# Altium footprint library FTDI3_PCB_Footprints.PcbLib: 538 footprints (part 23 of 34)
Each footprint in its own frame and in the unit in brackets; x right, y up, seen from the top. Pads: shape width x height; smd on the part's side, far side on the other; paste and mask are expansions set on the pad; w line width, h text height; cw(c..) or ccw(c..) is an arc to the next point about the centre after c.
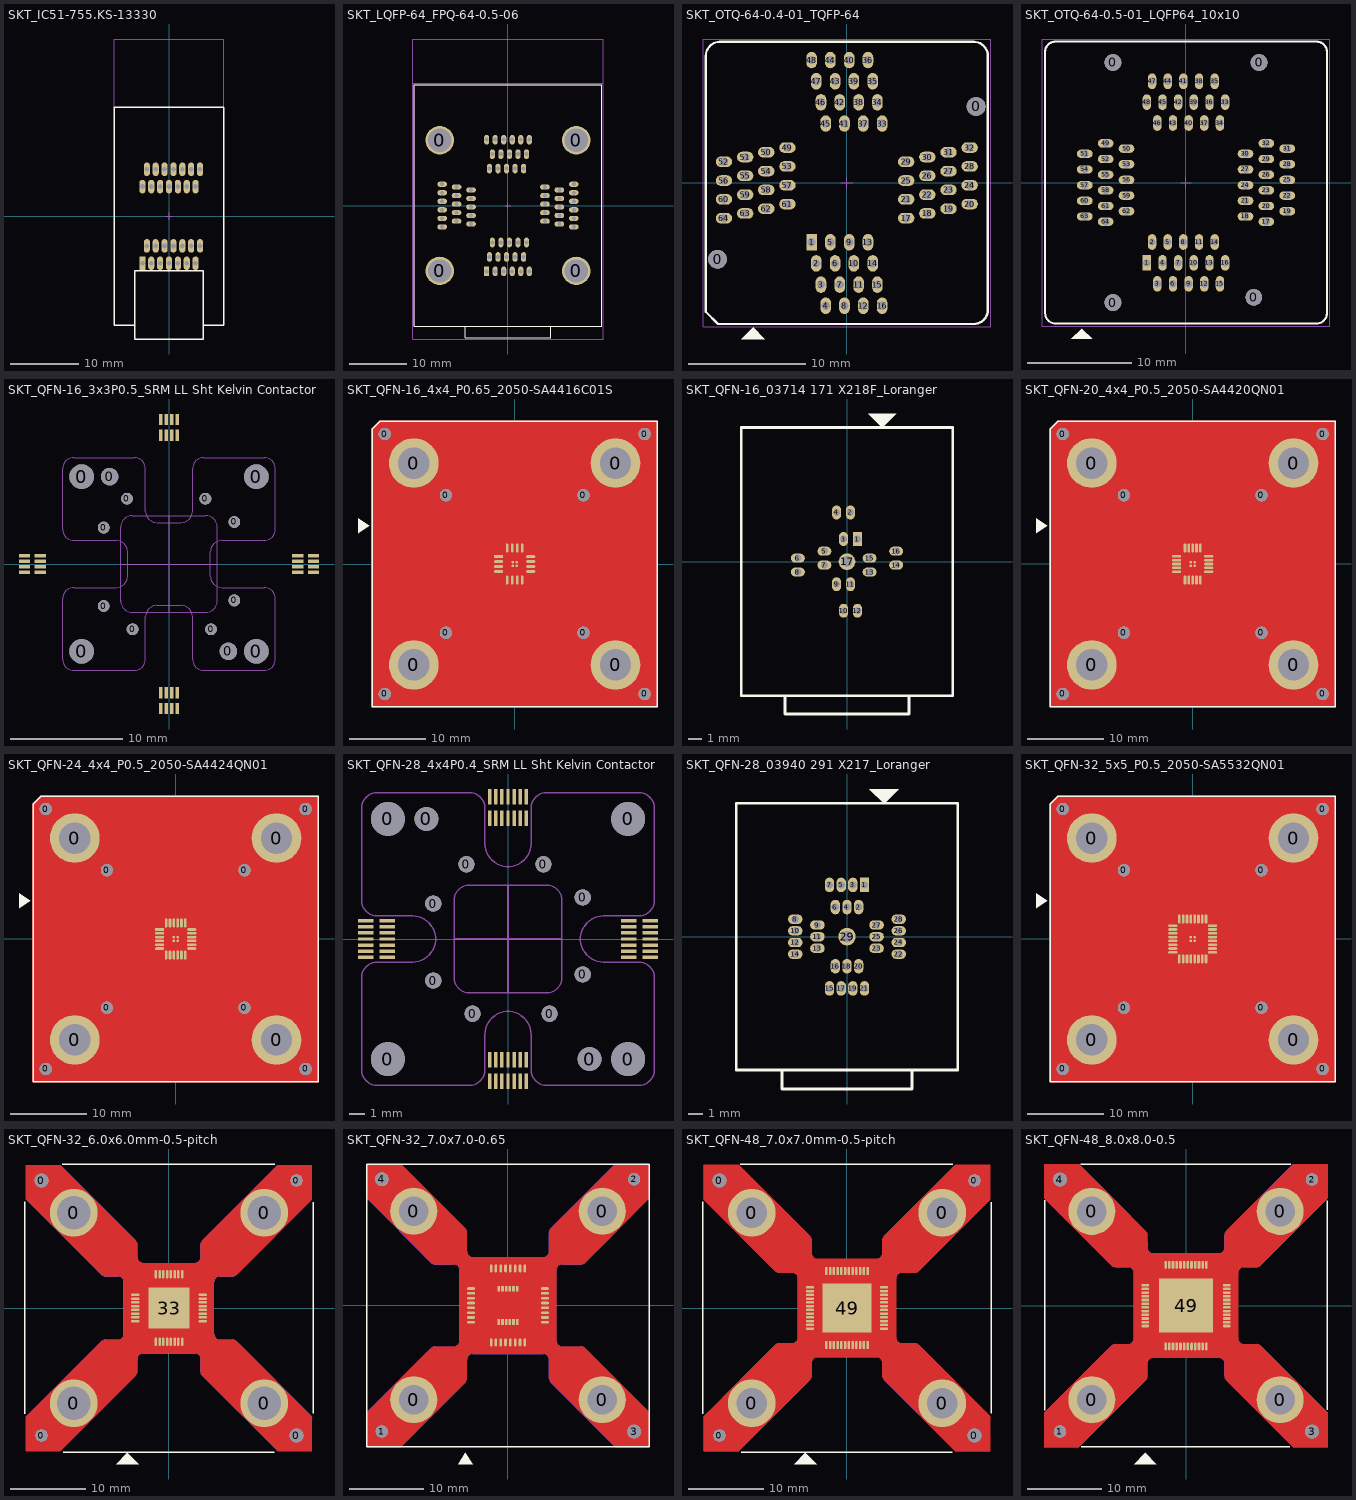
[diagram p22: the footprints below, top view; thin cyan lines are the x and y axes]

## SKT_IC51-755.KS-13330 [mm] "CLAMSHELL SOCKET 28PIN SSOP; Yamaichi - IC51-755.KS-13330"
height 20
pads (28):
  rect 0.9x2 hole 0.7: 1(-3.9,-6.89)
  oval 0.9x2 hole 0.7: 2(-3.25,-4.35) 3(-2.6,-6.89) 4(-1.95,-4.35) 5(-1.3,-6.89) 6(-0.65,-4.35) 7(0,-6.89) 8(0.65,-4.35) 9(1.3,-6.89) 10(1.95,-4.35) 11(2.6,-6.89) 12(3.25,-4.35) 13(3.9,-6.89) 14(4.55,-4.35) 15(4.55,6.89) 16(3.9,4.35) 17(3.25,6.89) 18(2.6,4.35) 19(1.95,6.89) 20(1.3,4.35) 21(0.65,6.89) 22(0,4.35) 23(-0.65,6.89) 24(-1.3,4.35) 25(-1.95,6.89) 26(-2.6,4.35) 27(-3.25,6.89) 28(-3.9,4.35)
Top Overlay:
  lines w0.2: -5,-16 -8,-16 -8,16 8,16 8,-16 5,-16 ; -5,-18 5,-18 5,-8 -5,-8 -5,-18
M15_Country_Yard:
  lines w0.1: -8,16 -8,26 8,26 8,16 ; -0.5,0 0.5,0 ; 0,-0.5 0,0.5

## SKT_LQFP-64_FPQ-64-0.5-06 [mm] "Test & Burn socket for LQFP-64, 0.5mm pitch, 10x10mm body. Enplas FPQ-64-0.5-06"
height 16
pads (68):
  round 5 hole 4.1: 0(-12,-11.5) 0(-12,11.5) 0(12,-11.5) 0(12,11.5)
  rect 0.9x1.7 hole 0.7: 1(-3.751,-11.582)
  oval 0.9x1.7 hole 0.7: 2(-3.251,-9.042) 3(-2.751,-6.502) 4(-2.251,-11.582) 5(-1.751,-9.042) 6(-1.251,-6.502) 7(-0.751,-11.582) 8(-0.251,-9.042) 9(0.249,-6.502) 10(0.749,-11.582) 11(1.249,-9.042) 12(1.749,-6.502) 13(2.249,-11.582) 14(2.749,-9.042) 15(3.249,-6.502) 16(3.749,-11.582) 33(3.749,11.582) 34(3.249,9.042) 35(2.749,6.502) 36(2.249,11.582) 37(1.749,9.042) 38(1.249,6.502) 39(0.749,11.582) 40(0.249,9.042) 41(-0.251,6.502) 42(-0.751,11.582) 43(-1.251,9.042) 44(-1.751,6.502) 45(-2.251,11.582) 46(-2.751,9.042) 47(-3.251,6.502) 48(-3.751,11.582)
  oval 1.7x0.9 hole 0.7: 17(11.582,-3.751) 18(9.042,-3.251) 19(6.502,-2.751) 20(11.582,-2.251) 21(9.042,-1.751) 22(6.502,-1.251) 23(11.582,-0.751) 24(9.042,-0.251) 25(6.502,0.249) 26(11.582,0.749) 27(9.042,1.249) 28(6.502,1.749) 29(11.582,2.249) 30(9.042,2.749) 31(6.502,3.249) 32(11.582,3.749) 49(-11.583,3.749) 50(-9.043,3.249) 51(-6.503,2.749) 52(-11.583,2.249) 53(-9.043,1.749) 54(-6.503,1.249) 55(-11.583,0.749) 56(-9.043,0.249) 57(-6.503,-0.251) 58(-11.583,-0.751) 59(-9.043,-1.251) 60(-6.503,-1.751) 61(-11.583,-2.251) 62(-9.043,-2.751) 63(-6.503,-3.251) 64(-11.583,-3.751)
Top Overlay:
  lines w0.2: -7.501,-21.25 -7.501,-23.24 7.499,-23.24 7.499,-21.25 ; -16.5,-21.25 -16.5,21.25 16.5,21.25 16.5,-21.25 -16.5,-21.25
M13_Assembly_Info:
  lines w0.1: -16.5,-21.25 -16.5,21.25 16.5,21.25 16.5,-21.25 -16.5,-21.25
M15_Country_Yard:
  lines w0.1: -16.74,21.51 16.75,21.51 ; -0.5,0 0.5,0 ; 0,-0.5 0,0.5 ; -16.74,-23.48 -16.74,-21.01 -16.74,21.25 -16.74,29.3 16.75,29.3 16.75,21.25 16.75,-21 16.75,-23.48 -16.74,-23.48

## SKT_OTQ-64-0.4-01_TQFP-64 [mm] "Test & Burn socket for TQFP-64 package"
height 19
pads (66):
  round 1.6 hole 1.6 unplated: 0(-11,-6.5) 0(11,6.5)
  rect 0.9x1.4 hole 0.7: 1(-3,-5.05)
  oval 0.9x1.4 hole 0.7: 2(-2.6,-6.85) 3(-2.2,-8.65) 4(-1.8,-10.45) 5(-1.4,-5.05) 6(-1,-6.85) 7(-0.6,-8.65) 8(-0.2,-10.45) 9(0.2,-5.05) 10(0.6,-6.85) 11(1,-8.65) 12(1.4,-10.45) 13(1.8,-5.05) 14(2.2,-6.85) 15(2.6,-8.65) 16(3,-10.45) 33(3,5.05) 34(2.6,6.85) 35(2.2,8.65) 36(1.8,10.45) 37(1.4,5.05) 38(1,6.85) 39(0.6,8.65) 40(0.2,10.45) 41(-0.2,5.05) 42(-0.6,6.85) 43(-1,8.65) 44(-1.4,10.45) 45(-1.8,5.05) 46(-2.2,6.85) 47(-2.6,8.65) 48(-3,10.45)
  oval 1.4x0.9 hole 0.7: 17(5.05,-3) 18(6.85,-2.6) 19(8.65,-2.2) 20(10.45,-1.8) 21(5.05,-1.4) 22(6.85,-1) 23(8.65,-0.6) 24(10.45,-0.2) 25(5.05,0.2) 26(6.85,0.6) 27(8.65,1) 28(10.45,1.4) 29(5.05,1.8) 30(6.85,2.2) 31(8.65,2.6) 32(10.45,3) 49(-5.05,3) 50(-6.85,2.6) 51(-8.65,2.2) 52(-10.45,1.8) 53(-5.05,1.4) 54(-6.85,1) 55(-8.65,0.6) 56(-10.45,0.2) 57(-5.05,-0.2) 58(-6.85,-0.6) 59(-8.65,-1) 60(-10.45,-1.4) 61(-5.05,-1.8) 62(-6.85,-2.2) 63(-8.65,-2.6) 64(-10.45,-3)
Top Overlay:
  region: -7.98,-12.28 -8.98,-13.28 -6.98,-13.28
  lines w0.2: -12,-10.96 -12,10.8 cw(c-10.8,10.8) -10.8,12 10.8,12 cw(c10.8,10.8) 12,10.8 12,-10.8 cw(c10.8,-10.8) 10.8,-12 -10.96,-12 -12,-10.96
M15_Country_Yard:
  lines w0.1: -0.5,0 0.5,0 ; 0,-0.5 0,0.5 ; -12.23,-12.25 -12.23,12.24 12.26,12.24 12.26,-12.25 -12.23,-12.25

## SKT_OTQ-64-0.5-01_LQFP64_10x10 [mm] "http://wvshare.com/product/OTQ-64-0.5-01.htm"
height 16
pads (68):
  round 1.6 hole 1.6 unplated: 0(-7,-11.5) 0(-7,11.5) 0(6.5,-11) 0(7,11.5)
  rect 0.8x1.5 hole 0.7: 1(-3.75,-7.7)
  oval 0.8x1.5 hole 0.7: 2(-3.25,-5.7) 3(-2.75,-9.7) 4(-2.25,-7.7) 5(-1.75,-5.7) 6(-1.25,-9.7) 7(-0.75,-7.7) 8(-0.25,-5.7) 9(0.25,-9.7) 10(0.75,-7.7) 11(1.25,-5.7) 12(1.75,-9.7) 13(2.25,-7.7) 14(2.75,-5.7) 15(3.25,-9.7) 16(3.75,-7.7) 33(3.75,7.7) 34(3.25,5.7) 35(2.75,9.7) 36(2.25,7.7) 37(1.75,5.7) 38(1.25,9.7) 39(0.75,7.7) 40(0.25,5.7) 41(-0.25,9.7) 42(-0.75,7.7) 43(-1.25,5.7) 44(-1.75,9.7) 45(-2.25,7.7) 46(-2.75,5.7) 47(-3.25,9.7) 48(-3.75,7.7)
  oval 1.5x0.8 hole 0.7: 17(7.7,-3.75) 18(5.7,-3.25) 19(9.7,-2.75) 20(7.7,-2.25) 21(5.7,-1.75) 22(9.7,-1.25) 23(7.7,-0.75) 24(5.7,-0.25) 25(9.7,0.25) 26(7.7,0.75) 27(5.7,1.25) 28(9.7,1.75) 29(7.7,2.25) 30(5.7,2.75) 31(9.7,3.25) 32(7.7,3.75) 49(-7.7,3.75) 50(-5.7,3.25) 51(-9.7,2.75) 52(-7.7,2.25) 53(-5.7,1.75) 54(-9.7,1.25) 55(-7.7,0.75) 56(-5.7,0.25) 57(-9.7,-0.25) 58(-7.7,-0.75) 59(-5.7,-1.25) 60(-9.7,-1.75) 61(-7.7,-2.25) 62(-5.7,-2.75) 63(-9.7,-3.25) 64(-7.7,-3.75)
Top Overlay:
  region: -10,-13.99 -11,-14.99 -9,-14.99
  lines w0.2: -13.5,-12.5 -13.5,12.51 cw(c-12.51,12.51) -12.51,13.5 12.51,13.5 cw(c12.51,12.51) 13.5,12.51 13.5,-12.51 cw(c12.51,-12.51) 12.51,-13.5 -12.5,-13.5 cw(c-12.5,-12.51) -13.49,-12.51
M15_Country_Yard:
  lines w0.1: -0.5,0 0.5,0 ; 0,-0.5 0,0.5 ; -13.75,-13.75 13.75,-13.75 13.75,13.35 13.75,13.75 -13.75,13.75 -13.75,-13.75
3D body: height 16, standoff 0, extent -13.5,-13.5 13.5,13.5
3D body: height 16, standoff 0, extent -5,-5 5,5

## SKT_QFN-16_3x3P0.5_SRM LL Sht Kelvin Contactor [mm] "Test Socket for QFN-16; 3x3mm package; 0.5mm pitch; SRM LL Sht Kelvin Contactor"
height 18
pads (46):
  round 2.2 hole 2.2 unplated: 0(-7.8,-7.8) 0(-7.8,7.8) 0(7.8,-7.8) 0(7.8,7.8)
  round 1.05 hole 1.05 unplated: 0(-5.83,-3.75) 0(-5.83,3.25) 0(-3.75,5.83) 0(-3.25,-5.83) 0(3.25,5.83) 0(3.75,-5.83) 0(5.83,-3.25) 0(5.83,3.75)
  round 1.55 hole 1.55 unplated: 0(-5.3,7.8) 0(5.3,-7.8)
  rect 1x0.3 smd: 1(11.49,-0.75) 1(12.89,-0.75) 2(11.49,-0.25) 2(12.89,-0.25) 3(11.49,0.25) 3(12.89,0.25) 4(11.49,0.75) 4(12.89,0.75) 9(-12.89,0.75) 9(-11.49,0.75) 10(-12.89,0.25) 10(-11.49,0.25) 11(-12.89,-0.25) 11(-11.49,-0.25) 12(-12.89,-0.75) 12(-11.49,-0.75)
  rect 0.3x1 smd: 5(0.75,11.49) 5(0.75,12.89) 6(0.25,11.49) 6(0.25,12.89) 7(-0.25,11.49) 7(-0.25,12.89) 8(-0.75,11.49) 8(-0.75,12.89) 13(-0.75,-12.89) 13(-0.75,-11.49) 14(-0.25,-12.89) 14(-0.25,-11.49) 15(0.25,-12.89) 15(0.25,-11.49) 16(0.75,-12.89) 16(0.75,-11.49)
Mechanical 1:
  lines w0.1: -4.3,-3.36 -4.3,3.3 cw(c-3.3,3.3) -3.3,4.3 3.3,4.3 cw(c3.3,3.3) 4.3,3.3 4.3,-3.3 cw(c3.3,-3.3) 3.3,-4.3 -3.3,-4.3 cw(c-3.3,-3.3) -4.3,-3.3
  text "area" at -3.19,-0.85 h0.8
  text "PCB Cutout" at -3.19,0.2 h0.8
M15_Country_Yard:
  lines w0.1: -4.3,0 4.3,0 ; -3.75,0 0,0 ; 0,-4.3 0,4.3 ; 0,-3.75 0,0 ; 0,3.75 0,0 ; 3.75,0 0,0 ; 0,0 0,-3.7 0,3.7 0,0 ; 0,0 -3.7,0 3.7,0 0,0 ; -9.5,-8.5 ccw(c-8.5,-8.5) -8.5,-9.5 -3.1,-9.5 ccw(c-3.1,-8.5) -2.1,-8.5 -2.1,-4.7 cw(c-1.1,-4.7) -1.1,-3.7 1.1,-3.7 cw(c1.1,-4.7) 2.1,-4.7 2.1,-8.5 ccw(c3.1,-8.5) 3.1,-9.5 8.5,-9.5 ccw(c8.5,-8.5) 9.5,-8.5 9.5,-3.1 ccw(c8.5,-3.1) 8.5,-2.1 4.7,-2.1 cw(c4.7,-1.1) 3.7,-1.1 3.7,1.1 cw(c4.7,1.1) 4.7,2.1 8.5,2.1 ccw(c8.5,3.1) 9.5,3.1 9.5,8.5 ccw(c8.5,8.5) 8.5,9.5 3.1,9.5 ccw(c3.1,8.5) 2.1,8.5 2.1,4.7 cw(c1.1,4.7) 1.1,3.7 -1.1,3.7 cw(c-1.1,4.7) -2.1,4.7 -2.1,8.5 ccw(c-3.1,8.5) -3.1,9.5 -8.5,9.5 ccw(c-8.5,8.5) -9.5,8.5 -9.5,3.1 ccw(c-8.5,3.1) -8.5,2.1 -4.7,2.1 cw(c-4.7,1.1) -3.7,1.1 -3.7,-1.1 cw(c-4.7,-1.1) -4.7,-2.1 -8.5,-2.1 ccw(c-8.5,-3.1) -9.5,-3.1 -9.5,-8.5

## SKT_QFN-16_4x4_P0.65_2050-SA4416C01S [mm] "Tai-Chen Precision Inc. QFN-16 4x4mm body; 0.65mm pitch; Test Socket; 2050-SA4416C01S"
height 6.6
pads (32):
  round 1.6 hole 1.6 unplated: 0(-17,-17) 0(-17,17) 0(-9,-9) 0(-9,9) 0(9,-9) 0(9,9) 0(17,-17) 0(17,17)
  round 6.5 hole 4.1: 0(-13.2,-13.2) 0(-13.2,13.2) 0(13.2,-13.2) 0(13.2,13.2)
  rect 1.2x0.35 smd: 1(-2.1,0.97)
  oval 1.2x0.35 smd: 2(-2.1,0.32) 3(-2.1,-0.33) 4(-2.1,-0.98) 9(2.1,-0.98) 10(2.1,-0.33) 11(2.1,0.32) 12(2.1,0.97)
  oval 0.35x1.2 smd: 5(-0.98,-2.1) 6(-0.33,-2.1) 7(0.32,-2.1) 8(0.97,-2.1) 13(0.97,2.1) 14(0.32,2.1) 15(-0.33,2.1) 16(-0.98,2.1)
  round 0.35 smd: 17(-0.25,-0.25) 17(-0.25,0.25) 17(0.25,-0.25) 17(0.25,0.25)
Top Layer:
  pour cut-out: 18.75,18.75 18.75,-18.75 -18.75,-18.75 -18.75,17.69 -17.69,18.75
Top Overlay:
  region: -19,5 -20.5,4 -20.5,6
  lines w0.2: -18.65,-18.65 -18.65,17.65 -17.65,18.65 18.65,18.65 18.65,-18.65 -18.65,-18.65
Top Solder:
  region: -18.55,-18.55 -18.55,17.61 -17.61,18.55 18.55,18.55 18.55,-18.55
M15_Country_Yard:
  lines w0.1: -0.5,0 0.5,0 ; 0,-0.5 0,0.5

## SKT_QFN-16_03714 171 X218F_Loranger [mm] "Test&Burn In Socket for QFN-16; 3x3mm package; 0.5mm pitch; Loranger part No. 03714 171 X218F"
height 18
pads (17):
  rect 0.65x1 hole 0.5: 1(0.75,1.625)
  oval 0.65x1 hole 0.5: 2(0.25,3.535) 3(-0.25,1.625) 4(-0.75,3.535) 9(-0.75,-1.625) 10(-0.25,-3.535) 11(0.25,-1.625) 12(0.75,-3.535)
  oval 1x0.65 hole 0.5: 5(-1.625,0.75) 6(-3.535,0.25) 7(-1.625,-0.25) 8(-3.535,-0.75) 13(1.625,-0.75) 14(3.535,-0.25) 15(1.625,0.25) 16(3.535,0.75)
  round 1.2 hole 0.8: 17(0,0)
Top Overlay:
  region: 2.54,9.615 1.54,10.615 3.54,10.615
  lines w0.2: -4.45,-9.66 -4.45,-10.96 4.45,-10.96 4.45,-9.66 ; -7.6,-9.65 7.6,-9.65 7.6,9.65 -7.6,9.65 -7.6,-9.65
M15_Country_Yard:
  lines w0.1: -0.5,0 0.5,0 ; 0,-0.5 0,0.5

## SKT_QFN-20_4x4_P0.5_2050-SA4420QN01 [mm] "Tai-Chen Precision Inc. QFN-20 4x4mm body; 0.5mm pitch; Test Socket; 2050-SA4420QN01"
height 6.6
pads (36):
  round 1.6 hole 1.6 unplated: 0(-17,-17) 0(-17,17) 0(-9,-9) 0(-9,9) 0(9,-9) 0(9,9) 0(17,-17) 0(17,17)
  round 6.5 hole 4.1: 0(-13.2,-13.2) 0(-13.2,13.2) 0(13.2,-13.2) 0(13.2,13.2)
  rect 1.2x0.35 smd: 1(-2.1,1)
  oval 1.2x0.35 smd: 2(-2.1,0.5) 3(-2.1,0) 4(-2.1,-0.5) 5(-2.1,-1) 11(2.1,-1) 12(2.1,-0.5) 13(2.1,0) 14(2.1,0.5) 15(2.1,1)
  oval 0.35x1.2 smd: 6(-1,-2.1) 7(-0.5,-2.1) 8(0,-2.1) 9(0.5,-2.1) 10(1,-2.1) 16(1,2.1) 17(0.5,2.1) 18(0,2.1) 19(-0.5,2.1) 20(-1,2.1)
  round 0.35 smd: 21(-0.25,-0.25) 21(-0.25,0.25) 21(0.25,-0.25) 21(0.25,0.25)
Top Layer:
  pour cut-out: -18.75,-18.75 -18.75,17.725 -17.725,18.75 18.75,18.75 18.75,-18.75
Top Overlay:
  region: -19,5 -20.5,4 -20.5,6
  lines w0.2: -18.65,-18.65 -18.65,17.65 -17.65,18.65 18.65,18.65 18.65,-18.65 -18.65,-18.65
Top Solder:
  region: -18.55,-18.55 -18.55,17.61 -17.61,18.55 18.55,18.55 18.55,-18.55
M15_Country_Yard:
  lines w0.1: -0.5,0 0.5,0 ; 0,-0.5 0,0.5

## SKT_QFN-24_4x4_P0.5_2050-SA4424QN01 [mm] "Tai-Chen Precision Inc. QFN-24 4x4mm body; 0.5mm pitch; Test Socket; 2050-SA4424QN01"
height 6.6
pads (40):
  round 1.6 hole 1.6 unplated: 0(-17,-17) 0(-17,17) 0(-9,-9) 0(-9,9) 0(9,-9) 0(9,9) 0(17,-17) 0(17,17)
  round 6.5 hole 4.1: 0(-13.2,-13.2) 0(-13.2,13.2) 0(13.2,-13.2) 0(13.2,13.2)
  rect 1.2x0.35 smd: 1(-2.1,1.25)
  oval 1.2x0.35 smd: 2(-2.1,0.75) 3(-2.1,0.25) 4(-2.1,-0.25) 5(-2.1,-0.75) 6(-2.1,-1.25) 13(2.1,-1.25) 14(2.1,-0.75) 15(2.1,-0.25) 16(2.1,0.25) 17(2.1,0.75) 18(2.1,1.25)
  oval 0.35x1.2 smd: 7(-1.25,-2.1) 8(-0.75,-2.1) 9(-0.25,-2.1) 10(0.25,-2.1) 11(0.75,-2.1) 12(1.25,-2.1) 19(1.25,2.1) 20(0.75,2.1) 21(0.25,2.1) 22(-0.25,2.1) 23(-0.75,2.1) 24(-1.25,2.1)
  round 0.35 smd: 25(-0.25,-0.25) 25(-0.25,0.25) 25(0.25,-0.25) 25(0.25,0.25)
Top Layer:
  pour cut-out: -18.75,-18.75 -18.75,17.725 -17.725,18.75 18.75,18.75 18.75,-18.75
  lines w0.2: -2.1,1.25 -2.1,1.25
Top Overlay:
  region: -19,5 -20.5,4 -20.5,6
  lines w0.2: -18.65,-18.65 18.65,-18.65 18.65,18.65 -17.65,18.65 -18.65,17.65 -18.65,-18.65
Top Solder:
  region: -18.55,-18.55 -18.55,17.61 -17.61,18.55 18.55,18.55 18.55,-18.55
M15_Country_Yard:
  lines w0.1: -0.5,0 0.5,0 ; 0,-0.5 0,0.5

## SKT_QFN-28_4x4P0.4_SRM LL Sht Kelvin Contactor [mm] "Test Socket for QFN-28; 4x4mm package; 0.4mm pitch; SRM LL Sht Kelvin Contactor"
height 18
pads (70):
  round 2.2 hole 2.2 unplated: 0(-7.8,-7.8) 0(-7.8,7.8) 0(7.8,-7.8) 0(7.8,7.8)
  round 1.55 hole 1.55 unplated: 0(-5.3,7.8) 0(5.3,-7.8)
  round 1.05 hole 1.05 unplated: 0(-4.85,-2.7) 0(-4.85,2.3) 0(-2.7,4.85) 0(-2.3,-4.85) 0(2.3,4.85) 0(2.7,-4.85) 0(4.85,-2.3) 0(4.85,2.7)
  rect 1x0.225 smd: 1(7.84,-1.2) 1(9.24,-1.2) 2(7.84,-0.8) 2(9.24,-0.8) 3(7.84,-0.4) 3(9.24,-0.4) 4(7.84,0) 4(9.24,0) 5(7.84,0.4) 5(9.24,0.4) 6(7.84,0.8) 6(9.24,0.8) 7(7.84,1.2) 7(9.24,1.2) 15(-9.24,1.2) 15(-7.84,1.2) 16(-9.24,0.8) 16(-7.84,0.8) 17(-9.24,0.4) 17(-7.84,0.4) 18(-9.24,0) 18(-7.84,0) 19(-9.24,-0.4) 19(-7.84,-0.4) 20(-9.24,-0.8) 20(-7.84,-0.8) 21(-9.24,-1.2) 21(-7.84,-1.2)
  rect 0.225x1 smd: 8(1.2,9.24) 8(1.2,7.84) 9(0.8,9.24) 9(0.8,7.84) 10(0.4,9.24) 10(0.4,7.84) 11(0,9.24) 11(0,7.84) 12(-0.4,9.24) 12(-0.4,7.84) 13(-0.8,9.24) 13(-0.8,7.84) 14(-1.2,9.24) 14(-1.2,7.84) 22(-1.2,-7.84) 22(-1.2,-9.24) 23(-0.8,-7.84) 23(-0.8,-9.24) 24(-0.4,-7.84) 24(-0.4,-9.24) 25(0,-7.84) 25(0,-9.24) 26(0.4,-7.84) 26(0.4,-9.24) 27(0.8,-7.84) 27(0.8,-9.24) 28(1.2,-7.84) 28(1.2,-9.24)
Mechanical 1:
  lines w0.1: -3.5,-2.5 ccw(c-2.5,-2.5) -2.5,-3.5 2.5,-3.5 ccw(c2.5,-2.5) 3.5,-2.5 3.5,2.5 ccw(c2.5,2.5) 2.5,3.5 -2.5,3.5 ccw(c-2.5,2.5) -3.5,2.5 -3.5,-2.5
  text "area" at -3.15,-0.33 h0.8
  text "PCB Cutout" at -3.15,0.72 h0.8
M15_Country_Yard:
  lines w0.1: -3.5,0 3.5,0 ; 0,-3.5 0,3.5 ; -9.5,-8.5 ccw(c-8.5,-8.5) -8.5,-9.5 -2.5,-9.5 ccw(c-2.5,-8.5) -1.5,-8.5 -1.5,-6.2 cw(c0,-6.2) 1.5,-6.2 1.5,-8.5 ccw(c2.5,-8.5) 2.5,-9.5 8.5,-9.5 ccw(c8.5,-8.5) 9.5,-8.5 9.5,-2.5 ccw(c8.5,-2.5) 8.5,-1.5 6.2,-1.5 cw(c6.2,0) 6.2,1.5 8.5,1.5 ccw(c8.5,2.5) 9.5,2.5 9.5,8.5 ccw(c8.5,8.5) 8.5,9.5 2.5,9.5 ccw(c2.5,8.5) 1.5,8.5 1.5,6.2 cw(c0,6.2) -1.5,6.2 -1.5,8.5 ccw(c-2.5,8.5) -2.5,9.5 -8.5,9.5 ccw(c-8.5,8.5) -9.5,8.5 -9.5,2.5 ccw(c-8.5,2.5) -8.5,1.5 -6.2,1.5 cw(c-6.2,0) -6.2,-1.5 -8.5,-1.5 ccw(c-8.5,-2.5) -9.5,-2.5 -9.5,-8.5

## SKT_QFN-28_03940 291 X217_Loranger [mm] "Test&Burn In Socket for QFN-28; 4x4mm package; 0.4mm pitch; Loranger part No. 03940 291 X217"
height 18
pads (29):
  rect 0.65x1 hole 0.5: 1(1.2,3.55)
  oval 0.65x1 hole 0.5: 2(0.8,2.03) 3(0.4,3.55) 4(0,2.03) 5(-0.4,3.55) 6(-0.8,2.03) 7(-1.2,3.55) 15(-1.2,-3.55) 16(-0.8,-2.03) 17(-0.4,-3.55) 18(0,-2.03) 19(0.4,-3.55) 20(0.8,-2.03) 21(1.2,-3.55)
  oval 1x0.65 hole 0.5: 8(-3.55,1.2) 9(-2.03,0.8) 10(-3.55,0.4) 11(-2.03,0) 12(-3.55,-0.4) 13(-2.03,-0.8) 14(-3.55,-1.2) 22(3.55,-1.2) 23(2.03,-0.8) 24(3.55,-0.4) 25(2.03,0) 26(3.55,0.4) 27(2.03,0.8) 28(3.55,1.2)
  round 1.2 hole 0.8: 29(0,0)
Top Overlay:
  region: 2.54,9.13 1.54,10.13 3.54,10.13
  lines w0.2: -4.45,-9.15 -4.45,-10.45 4.45,-10.45 4.45,-9.15 ; -7.6,-9.15 -7.6,9.15 7.6,9.15 7.6,-9.15 -7.6,-9.15
M15_Country_Yard:
  lines w0.1: -0.5,0 0.5,0 ; 0,-0.5 0,0.5

## SKT_QFN-32_5x5_P0.5_2050-SA5532QN01 [mm] "Tai-Chen Precision Inc. QFN-32 5x5mm body; 0.5mm pitch; Test Socket; 2050-SA5532QN01"
height 6.6
pads (48):
  round 1.6 hole 1.6 unplated: 0(-17,-17) 0(-17,17) 0(-9,-9) 0(-9,9) 0(9,-9) 0(9,9) 0(17,-17) 0(17,17)
  round 6.5 hole 4.1: 0(-13.2,-13.2) 0(-13.2,13.2) 0(13.2,-13.2) 0(13.2,13.2)
  oval 1.2x0.35 smd: 1(-2.6,1.75) 2(-2.6,1.25) 3(-2.6,0.75) 4(-2.6,0.25) 5(-2.6,-0.25) 6(-2.6,-0.75) 7(-2.6,-1.25) 8(-2.6,-1.75) 17(2.6,-1.75) 18(2.6,-1.25) 19(2.6,-0.75) 20(2.6,-0.25) 21(2.6,0.25) 22(2.6,0.75) 23(2.6,1.25) 24(2.6,1.75)
  oval 0.35x1.2 smd: 9(-1.75,-2.6) 10(-1.25,-2.6) 11(-0.75,-2.6) 12(-0.25,-2.6) 13(0.25,-2.6) 14(0.75,-2.6) 15(1.25,-2.6) 16(1.75,-2.6) 25(1.75,2.61) 26(1.25,2.61) 27(0.75,2.61) 28(0.25,2.61) 29(-0.25,2.61) 30(-0.75,2.61) 31(-1.25,2.61) 32(-1.75,2.61)
  round 0.35 smd: 33(-0.25,-0.25) 33(-0.25,0.25) 33(0.25,-0.25) 33(0.25,0.25)
Top Layer:
  pour cut-out: -18.75,-18.75 -18.75,17.725 -17.725,18.75 18.75,18.75 18.75,-18.75
Top Overlay:
  region: -19,5 -20.5,4 -20.5,6
  lines w0.2: -18.65,-18.65 18.65,-18.65 18.65,18.65 -17.65,18.65 -18.65,17.65 -18.65,-18.65
Top Solder:
  region: -18.55,-18.55 -18.55,17.61 -17.61,18.55 18.55,18.55 18.55,-18.55
M15_Country_Yard:
  lines w0.1: -0.5,0 0.5,0 ; 0,-0.5 0,0.5

## SKT_QFN-32_6.0x6.0mm-0.5-pitch [mm] "Load Board Socket for QFN-32; 6.0x6.0mm-0.5mm-pitch; Johnstech; Pad ROL(tm)200 series JTI-LBD-32-QFN-6.0X6.0-0.50"
height 5.5
pads (41):
  round 1.61 hole 1.61 unplated: 0(-17,-17) 0(17,17)
  round 1.85 hole 1.85 unplated: 0(-17,17) 0(17,-17)
  round 6.35 hole 4.5: 0(-12.7,-12.7) 0(-12.7,12.7) 0(12.7,-12.7) 0(12.7,12.7)
  oval 0.356x1.1 smd: 1(-1.75,-4.5) 2(-1.25,-4.5) 3(-0.75,-4.5) 4(-0.25,-4.5) 5(0.25,-4.5) 6(0.75,-4.5) 7(1.25,-4.5) 8(1.75,-4.5) 17(1.75,4.5) 18(1.25,4.5) 19(0.75,4.5) 20(0.25,4.5) 21(-0.25,4.5) 22(-0.75,4.5) 23(-1.25,4.5) 24(-1.75,4.5)
  oval 1.1x0.356 smd: 9(4.5,-1.75) 10(4.5,-1.25) 11(4.5,-0.75) 12(4.5,-0.25) 13(4.5,0.25) 14(4.5,0.75) 15(4.5,1.25) 16(4.5,1.75) 25(-4.5,1.75) 26(-4.5,1.25) 27(-4.5,0.75) 28(-4.5,0.25) 29(-4.5,-0.25) 30(-4.5,-0.75) 31(-4.5,-1.25) 32(-4.5,-1.75)
  rect 5.45x5.45 smd: 33(0,0)
Top Layer:
  pour cut-out: -19.049,-19.05 -14.478,-19.05 -4.47,-9.042 -4.292,-8.763 -4.249,-8.482 -4.249,-6.745 -4.19,-6.477 -4.038,-6.223 -3.784,-6.045 -3.505,-6 3.48,-6 3.48,-6.03 3.785,-6.096 4.039,-6.248 4.192,-6.502 4.251,-6.8 4.251,-8.821 14.479,-19.05 19.051,-19.05 19.051,-14.479 9.556,-4.984 9.055,-4.483 8.814,-4.293 8.489,-4.249 6.8,-4.25 6.502,-4.191 6.325,-4.089 6.172,-3.937 6.071,-3.81 6,-3.45 6,3.607 6.172,3.937 6.375,4.115 6.528,4.191 6.8,4.25 8.484,4.25 8.814,4.293 9.049,4.484 9.22,4.623 19.051,14.48 19.051,19.05 14.479,19.05 4.481,9.052 4.319,8.788 4.251,8.482 4.251,7.3 4.242,7.061 4.25,6.8 4.14,6.401 3.937,6.198 3.658,6.045 3.454,6 -3.454,6 -3.759,6.071 -3.962,6.172 -4.115,6.35 -4.242,6.604 -4.25,6.883 -4.249,7.3 -4.249,8.482 -4.292,8.788 -4.483,9.055 -14.478,19.05 -19.049,19.05 -19.049,14.479 -9.052,4.481 -8.788,4.293 -8.483,4.25 -6.799,4.25 -6.451,4.166 -6.172,3.988 -6.019,3.708 -5.999,3.429 -5.999,-3.45 -6.045,-3.734 -6.197,-3.988 -6.476,-4.166 -6.799,-4.25 -8.483,-4.25 -8.839,-4.343 -9.048,-4.484 -19.049,-14.479
Top Overlay:
  region: -5.56,-19.3 -4.06,-20.8 -7.06,-20.8
  lines w0.2: -19.2,-14.13 -19.2,14.195 ; -14.205,19.2 14.12,19.2 ; -14.13,-19.2 14.02,-19.2 ; 19.2,-14.03 19.2,14.12
Top Solder:
  region: -19.075,19.05 -14.503,19.05 -4.877,9.398 -4.42,8.966 -4.343,8.763 -4.301,8.533 -4.301,6.851 -4.267,6.629 -4.216,6.477 -4.013,6.223 -3.81,6.096 -3.505,6.051 3.404,6.051 3.658,6.071 3.861,6.198 4.089,6.401 4.191,6.629 4.216,7.188 4.216,8.407 4.242,8.611 4.293,8.788 4.369,8.941 4.47,9.093 14.453,19.05 19.025,19.05 19.025,14.478 9.296,4.75 9.049,4.484 8.814,4.318 8.484,4.25 6.8,4.25 6.401,4.14 6.147,3.962 6,3.607 6,-3.45 6.071,-3.785 6.248,-4.013 6.452,-4.166 6.8,-4.25 8.489,-4.249 8.788,-4.293 9.055,-4.483 9.271,-4.75 19.025,-14.503 19.025,-19.05 14.478,-19.05 14.453,-19.075 4.216,-8.839 4.216,-6.756 4.115,-6.426 3.962,-6.172 3.759,-6.045 3.454,-5.994 -3.505,-5.994 -3.912,-6.096 -4.216,-6.426 -4.267,-6.756 -4.267,-8.839 -14.503,-19.075 -14.529,-19.05 -19.101,-19.05 -19.101,-14.529 -9.042,-4.47 -8.839,-4.318 -8.661,-4.267 -8.484,-4.242 -6.833,-4.242 -6.579,-4.191 -6.426,-4.115 -6.274,-4.013 -6.071,-3.734 -6.045,3.556 -6.172,3.785 -6.274,3.912 -6.452,4.089 -6.579,4.191 -6.68,4.242 -6.883,4.267 -8.865,4.267 -19.075,14.478
  lines w0.1: -9.067,4.496 -19.05,14.479 -19.05,19.05 -14.479,19.05 -4.48,9.052 ; -9.049,-4.484 cw(c-8.483,-5.05) -8.483,-4.25 ; -9.049,-4.478 -19.05,-14.479 -19.05,-19.05 -14.479,-19.05 -4.48,-9.052 ; -9.049,4.484 ccw(c-8.484,5.05) -8.484,4.25 -6.8,4.25 cw(c-6.8,3.45) -6,3.45 -6,-3.531 ; -8.476,-4.25 -6.8,-4.25 ccw(c-6.8,-3.45) -6,-3.45 ; -4.484,-9.048 ccw(c-5.05,-8.482) -4.25,-8.482 -4.25,-6.792 ; -4.484,9.048 cw(c-5.05,8.482) -4.25,8.482 -4.25,6.8 ccw(c-3.45,6.8) -3.45,6 ; -4.25,-6.8 cw(c-3.45,-6.8) -3.45,-6 ; -3.531,-6 3.454,-6 ; -3.454,6 3.454,6 ; 3.45,-6 cw(c3.45,-6.8) 4.25,-6.8 4.25,-8.49 ccw(c5.05,-8.49) 4.484,-9.056 14.479,-19.05 19.05,-19.05 19.05,-14.479 9.055,-4.483 ccw(c8.489,-5.049) 8.489,-4.249 6.782,-4.25 ; 3.45,6 ccw(c3.45,6.8) 4.25,6.8 ; 4.25,7.3 4.25,8.482 cw(c5.05,8.482) 4.484,9.048 ; 4.48,9.052 14.479,19.05 19.05,19.05 19.05,14.48 9.052,4.482 ; 6,3.45 cw(c6.8,3.45) 6.8,4.25 8.484,4.25 ccw(c8.484,5.05) 9.049,4.484 ; 6,3.607 6,-3.45 ccw(c6.8,-3.45) 6.8,-4.25
M13_Assembly_Info:
  lines w0.1: -9.052,-4.481 -19.05,-14.479 -19.05,-19.05 -14.479,-19.05 -4.471,-9.042 ; -9.052,4.481 -19.05,14.479 -19.05,19.05 -14.479,19.05 -4.483,9.055 ; -9.049,-4.484 cw(c-8.483,-5.05) -8.483,-4.25 ; -9.049,4.484 ccw(c-8.484,5.05) -8.484,4.25 -6.8,4.25 cw(c-6.8,3.45) -6,3.45 -6,-3.45 cw(c-6.8,-3.45) -6.8,-4.25 -8.476,-4.25 ; -4.484,-9.048 ccw(c-5.05,-8.482) -4.25,-8.482 -4.25,-6.792 ; -4.484,9.048 cw(c-5.05,8.482) -4.25,8.482 -4.25,6.8 ccw(c-3.45,6.8) -3.45,6 ; -4.25,-6.8 cw(c-3.45,-6.8) -3.45,-6 ; -3.505,-6 3.48,-6 ; -3.454,6 3.454,6 ; 3.45,-6 cw(c3.45,-6.8) 4.25,-6.8 4.25,-8.49 ccw(c5.05,-8.49) 4.484,-9.056 14.479,-19.05 19.05,-19.05 19.05,-14.479 9.055,-4.483 ccw(c8.489,-5.049) 8.489,-4.249 6.8,-4.25 cw(c6.8,-3.45) 6,-3.45 6,3.607 ; 3.45,6 ccw(c3.45,6.8) 4.25,6.8 4.25,8.482 cw(c5.05,8.482) 4.484,9.048 ; 4.48,9.052 14.479,19.05 19.05,19.05 19.05,14.48 9.064,4.494 ; 6,3.45 cw(c6.8,3.45) 6.8,4.25 8.484,4.25 ccw(c8.484,5.05) 9.049,4.484
M15_Country_Yard:
  lines w0.1: -0.5,0 0.5,0 ; 0,-0.5 0,0.5

## SKT_QFN-32_7.0x7.0-0.65 [mm] "Load Board Socket for QFN-32; 7.0 x 7.0mm; 0.65mm pitch; Johnstech; Pad ROL(tm)200 series Production Test Contactor"
height 5.5
pads (52):
  round 6.35 hole 4: 0(-12.7,-12.7) 0(-12.7,12.7) 0(12.7,-12.7) 0(12.7,12.7)
  round 1.65 hole 1.65 unplated: 1(-17,-17) 2(17,17)
  oval 0.356x1.07 smd: 1(-2.275,-4.985) 2(-1.625,-4.985) 3(-0.975,-4.985) 4(-0.325,-4.985) 5(0.325,-4.985) 6(0.975,-4.985) 7(1.625,-4.985) 8(2.275,-4.985) 17(2.275,4.98) 18(1.625,4.98) 19(0.975,4.98) 20(0.325,4.98) 21(-0.325,4.98) 22(-0.975,4.98) 23(-1.625,4.98) 24(-2.275,4.98)
  round 1.85 hole 1.85 unplated: 3(17,-17) 4(-17,17)
  oval 1.07x0.356 smd: 9(4.98,-2.275) 10(4.98,-1.625) 11(4.98,-0.975) 12(4.98,-0.325) 13(4.98,0.325) 14(4.98,0.975) 15(4.98,1.625) 16(4.98,2.275) 25(-4.98,2.275) 26(-4.98,1.625) 27(-4.98,0.975) 28(-4.98,0.325) 29(-4.98,-0.325) 30(-4.98,-0.975) 31(-4.98,-1.625) 32(-4.98,-2.275)
  rect 0.36x0.8 smd: 33(-1.25,-2.25) 33(-1.25,2.25) 33(-0.75,-2.25) 33(-0.75,2.25) 33(-0.25,-2.25) 33(-0.25,2.25) 33(0.25,-2.25) 33(0.25,2.25) 33(0.75,-2.25) 33(0.75,2.25) 33(1.25,-2.25) 33(1.25,2.25)
Top Layer:
  pour cut-out: -19.05,-19.05 -19.05,-14.48 -11.13,-6.545 -10.62,-6.045 -10.09,-5.595 -9.385,-5.54 -8.65,-5.545 -7.21,-5.54 -6.94,-5.465 -6.695,-5.295 -6.56,-5.065 -6.495,-4.825 -6.495,4.885 -6.59,5.125 -6.735,5.345 -6.94,5.475 -7.165,5.555 -9.765,5.555 -10.105,5.61 -10.38,5.82 -10.65,6.095 -11.205,6.64 -12.365,7.81 -14.6,10.035 -19.045,14.485 -19.045,19.06 -14.48,19.06 -10.02,14.605 -7.76,12.35 -6.65,11.235 -5.8,10.385 -5.595,10.08 -5.545,9.86 -5.54,9.48 -5.545,7.275 -5.485,6.98 -5.31,6.71 -5.05,6.56 -4.77,6.5 4.8,6.5 4.8,6.505 5.075,6.57 5.325,6.71 5.49,6.98 5.56,7.265 5.555,8.71 5.55,9.45 5.55,9.83 5.605,10.135 5.82,10.415 6.1,10.69 6.67,11.255 7.805,12.375 10.025,14.605 14.48,19.055 19.05,19.055 19.05,14.48 14.605,10.03 12.36,7.79 11.245,6.68 10.68,6.11 10.395,5.825 10.26,5.7 10.11,5.605 9.94,5.57 9.765,5.55 9.4,5.555 7.265,5.555 6.965,5.485 6.715,5.315 6.565,5.065 6.505,4.795 6.505,-4.78 6.51,-4.78 6.56,-5.05 6.72,-5.31 6.965,-5.47 7.275,-5.545 9.81,-5.545 10.12,-5.6 10.395,-5.81 10.685,-6.1 11.25,-6.67 12.365,-7.785 14.6,-10.015 19.055,-14.475 19.055,-19.045 14.485,-19.045 10.015,-14.565 7.76,-12.325 6.64,-11.21 6.075,-10.645 5.78,-10.345 5.6,-10.08 5.55,-9.73 5.555,-9.355 5.555,-8.62 5.55,-7.17 5.46,-6.91 5.305,-6.695 5.095,-6.565 4.875,-6.495 -4.825,-6.495 -5.09,-6.58 -5.325,-6.73 -5.48,-6.965 -5.545,-7.215 -5.545,-8.655 -5.54,-9.41 -5.545,-9.785 -5.6,-10.095 -5.785,-10.375 -6.065,-10.655 -6.645,-11.225 -7.775,-12.335 -10.04,-14.585 -14.48,-19.05
Top Overlay:
  region: -5.73,-19.87 -4.73,-21.37 -6.73,-21.37
  lines w0.2: -19.05,-19.05 -19.05,19.05 19.05,19.05 19.05,-19.05 -19.05,-19.05
Top Solder:
  drawing of 49 lines, arcs and shapes, not listed
M13_Assembly_Info:
  lines w0.1: 19.05,14.479 19.05,19.05 14.479,19.05 5.784,10.356 ccw(c6.35,9.79) 5.55,9.79 5.55,7.3 cw(c4.75,7.3) 4.75,6.5 -4.75,6.5 cw(c-4.75,7.3) -5.55,7.3 -5.55,9.79 ccw(c-6.35,9.79) -5.784,10.356 -14.479,19.05 -19.05,19.05 -19.05,14.479 -10.356,5.784 ccw(c-9.79,6.35) -9.79,5.55 -7.3,5.55 cw(c-7.3,4.75) -6.5,4.75 -6.5,-4.75 cw(c-7.3,-4.75) -7.3,-5.55 -9.79,-5.55 ccw(c-9.79,-6.35) -10.356,-5.784 -19.05,-14.479 -19.05,-19.05 -14.479,-19.05 -5.784,-10.356 ccw(c-6.35,-9.79) -5.55,-9.79 -5.55,-7.3 cw(c-4.75,-7.3) -4.75,-6.5 4.75,-6.5 cw(c4.75,-7.3) 5.55,-7.3 5.55,-9.79 ccw(c6.35,-9.79) 5.784,-10.356 14.479,-19.05 19.05,-19.05 19.05,-14.479 10.356,-5.784 ccw(c9.79,-6.35) 9.79,-5.55 7.3,-5.55 cw(c7.3,-4.75) 6.5,-4.75 6.5,4.75 cw(c7.3,4.75) 7.3,5.55 9.79,5.55 ccw(c9.79,6.35) 10.356,5.784 19.05,14.48 ; -3.75,-3.75 -3.75,3.75 3.75,3.75 3.75,-3.75 -3.75,-3.75
M15_Country_Yard:
  lines w0.1: -0.5,0 0.5,0 ; 0,-0.5 0,0.5

## SKT_QFN-48_7.0x7.0mm-0.5-pitch [mm] "Load Board Socket for QFN-48; 7.0x7.0mm-0.5mm-pitch; Johnstech; Pad ROL(tm)200 series JTI-TS-48-QFN-7.0X7.0-0.50-7884-0201;"
height 5.5
pads (57):
  round 1.61 hole 1.61 unplated: 0(-17,-17) 0(17,17)
  round 1.85 hole 1.85 unplated: 0(-17,17) 0(17,-17)
  round 6.35 hole 4.1: 0(-12.7,-12.7) 0(-12.7,12.7) 0(12.7,-12.7) 0(12.7,12.7)
  oval 0.356x1.1 smd: 1(-2.75,-4.94) 2(-2.25,-4.94) 3(-1.75,-4.94) 4(-1.25,-4.94) 5(-0.75,-4.94) 6(-0.25,-4.94) 7(0.25,-4.94) 8(0.75,-4.94) 9(1.25,-4.94) 10(1.75,-4.94) 11(2.25,-4.94) 12(2.75,-4.94) 25(2.75,4.94) 26(2.25,4.94) 27(1.75,4.94) 28(1.25,4.94) 29(0.75,4.94) 30(0.25,4.94) 31(-0.25,4.94) 32(-0.75,4.94) 33(-1.25,4.94) 34(-1.75,4.94) 35(-2.25,4.94) 36(-2.75,4.94)
  oval 1.1x0.356 smd: 13(4.94,-2.75) 14(4.94,-2.25) 15(4.94,-1.75) 16(4.94,-1.25) 17(4.94,-0.75) 18(4.94,-0.25) 19(4.94,0.25) 20(4.94,0.75) 21(4.94,1.25) 22(4.94,1.75) 23(4.94,2.25) 24(4.94,2.75) 37(-4.94,2.75) 38(-4.94,2.25) 39(-4.94,1.75) 40(-4.94,1.25) 41(-4.94,0.75) 42(-4.94,0.25) 43(-4.94,-0.25) 44(-4.94,-0.75) 45(-4.94,-1.25) 46(-4.94,-1.75) 47(-4.94,-2.25) 48(-4.94,-2.75)
  rect 6.5x6.5 smd: 49(0,0)
Top Layer:
  pour cut-out: 191 vertices and 0 holes, not listed, extent -19.1,-19.1 19.1,19.1
Top Overlay:
  region: -5.56,-19.3 -4.06,-20.8 -7.06,-20.8
  lines w0.2: -19.2,-14.13 -19.2,14.195 ; -14.205,19.2 14.12,19.2 ; -14.13,-19.2 14.02,-19.2 ; 19.2,-14.03 19.2,14.12
Top Solder:
  region: -19.05,-19.05 -14.479,-19.05 -9.871,-14.443 -7.52,-12.08 -6.165,-10.736 -4.984,-9.556 -4.82,-9.31 -4.75,-8.99 -4.75,-7.3 -4.7,-6.97 -4.52,-6.72 -4.28,-6.57 -3.95,-6.5 3.95,-6.5 4.31,-6.58 4.56,-6.77 4.71,-7.01 4.75,-7.3 4.75,-8.99 4.83,-9.32 4.984,-9.556 14.479,-19.05 19.05,-19.05 19.05,-14.479 10.056,-5.484 9.82,-5.26 9.556,-4.984 9.29,-4.81 8.99,-4.75 7.3,-4.75 6.99,-4.7 6.73,-4.52 6.55,-4.26 6.5,-3.95 6.5,3.95 6.55,4.21 6.67,4.46 6.93,4.68 7.3,4.75 8.99,4.75 9.31,4.81 9.556,4.984 9.71,5.14 9.84,5.27 10.056,5.486 10.864,6.294 12.09,7.56 14.38,9.85 19.05,14.48 19.05,19.05 14.479,19.05 5.25,9.821 4.984,9.556 4.77,9.22 4.75,8.99 4.75,7.96 4.75,7.3 4.7,7 4.55,6.76 4.28,6.57 3.95,6.5 -3.95,6.5 -4.33,6.55 -4.55,6.75 -4.68,6.96 -4.76,7.06 -4.75,7.3 -4.75,7.84 -4.75,8.99 -4.82,9.31 -4.984,9.556 -5.28,9.83 -5.484,10.056 -14.479,19.05 -19.05,19.05 -19.05,14.479 -9.56,4.989 -9.3,4.81 -8.99,4.75 -7.3,4.75 -6.93,4.67 -6.69,4.49 -6.55,4.24 -6.5,3.95 -6.5,-3.95 -6.55,-4.26 -6.71,-4.5 -6.96,-4.7 -7.3,-4.75 -8.99,-4.75 -9.29,-4.81 -9.556,-4.984 -19.05,-14.479
  lines w0.1: -19.05,-19.05 -14.479,-19.05 -4.984,-9.556 ccw(c-5.55,-8.99) -4.75,-8.99 -4.75,-7.3 cw(c-3.95,-7.3) -3.95,-6.5 3.95,-6.5 cw(c3.95,-7.3) 4.75,-7.3 4.75,-8.99 ccw(c5.55,-8.99) 4.984,-9.556 14.479,-19.05 19.05,-19.05 19.05,-14.479 9.556,-4.984 ccw(c8.99,-5.55) 8.99,-4.75 7.3,-4.75 cw(c7.3,-3.95) 6.5,-3.95 6.5,3.95 cw(c7.3,3.95) 7.3,4.75 8.99,4.75 ccw(c8.99,5.55) 9.556,4.984 19.05,14.48 19.05,19.05 14.479,19.05 4.984,9.556 ccw(c5.55,8.99) 4.75,8.99 4.75,7.3 cw(c3.95,7.3) 3.95,6.5 -3.95,6.5 cw(c-3.95,7.3) -4.75,7.3 -4.75,8.99 ccw(c-5.55,8.99) -4.984,9.556 -14.479,19.05 -19.05,19.05 -19.05,14.479 -9.556,4.984 ccw(c-8.99,5.55) -8.99,4.75 -7.3,4.75 cw(c-7.3,3.95) -6.5,3.95 -6.5,-3.95 cw(c-7.3,-3.95) -7.3,-4.75 -8.99,-4.75 ccw(c-8.99,-5.55) -9.556,-4.984 -19.05,-14.479 -19.05,-19.05
M13_Assembly_Info:
  lines w0.1: -19.05,-19.05 -19.05,-14.479 -9.556,-4.984 cw(c-8.99,-5.55) -8.99,-4.75 -7.3,-4.75 ccw(c-7.3,-3.95) -6.5,-3.95 -6.5,3.95 ccw(c-7.3,3.95) -7.3,4.75 -8.99,4.75 cw(c-8.99,5.55) -9.556,4.984 -19.05,14.479 -19.05,19.05 -14.479,19.05 -4.984,9.556 cw(c-5.55,8.99) -4.75,8.99 -4.75,7.3 ccw(c-3.95,7.3) -3.95,6.5 3.95,6.5 ccw(c3.95,7.3) 4.75,7.3 4.75,8.99 cw(c5.55,8.99) 4.984,9.556 14.479,19.05 19.05,19.05 19.05,14.48 9.555,4.985 cw(c8.99,5.55) 8.99,4.75 7.3,4.75 ccw(c7.3,3.95) 6.5,3.95 6.5,-3.95 ccw(c7.3,-3.95) 7.3,-4.75 8.99,-4.75 cw(c8.99,-5.55) 9.556,-4.984 19.05,-14.479 19.05,-19.05 14.479,-19.05 4.984,-9.556 cw(c5.55,-8.99) 4.75,-8.99 4.75,-7.3 ccw(c3.95,-7.3) 3.95,-6.5 -3.95,-6.5 ccw(c-3.95,-7.3) -4.75,-7.3 -4.75,-8.99 cw(c-5.55,-8.99) -4.984,-9.556 -14.479,-19.05 -19.05,-19.05
M15_Country_Yard:
  lines w0.1: -0.5,0 0.5,0 ; 0,-0.5 0,0.5

## SKT_QFN-48_8.0x8.0-0.5 [mm] "Load Board Socket for QFN-48; 8.0 x 8.0mm; 0.5mm pitch; Johnstech; Pad ROL(tm)200 series JTI-48-QFN-8.0X8.0-0.50-6022; Production Test Contactor"
height 5.5
pads (69):
  round 6.35 hole 4: 0(-12.7,-12.7) 0(-12.7,12.7) 0(12.7,-12.7) 0(12.7,12.7)
  round 1.65 hole 1.65 unplated: 1(-17,-17) 2(17,17)
  oval 0.356x1.07 smd: 1(-2.75,-5.5) 2(-2.25,-5.5) 3(-1.75,-5.5) 4(-1.25,-5.5) 5(-0.75,-5.5) 6(-0.25,-5.5) 7(0.25,-5.5) 8(0.75,-5.5) 9(1.25,-5.5) 10(1.75,-5.5) 11(2.25,-5.5) 12(2.75,-5.5) 25(2.75,5.5) 26(2.25,5.5) 27(1.75,5.5) 28(1.25,5.5) 29(0.75,5.5) 30(0.25,5.5) 31(-0.25,5.5) 32(-0.75,5.5) 33(-1.25,5.5) 34(-1.75,5.5) 35(-2.25,5.5) 36(-2.75,5.5)
  round 1.85 hole 1.85 unplated: 3(17,-17) 4(-17,17)
  oval 1.07x0.356 smd: 13(5.5,-2.75) 14(5.5,-2.25) 15(5.5,-1.75) 16(5.5,-1.25) 17(5.5,-0.75) 18(5.5,-0.25) 19(5.5,0.25) 20(5.5,0.75) 21(5.5,1.25) 22(5.5,1.75) 23(5.5,2.25) 24(5.5,2.75) 37(-5.5,2.75) 38(-5.5,2.25) 39(-5.5,1.75) 40(-5.5,1.25) 41(-5.5,0.75) 42(-5.5,0.25) 43(-5.5,-0.25) 44(-5.5,-0.75) 45(-5.5,-1.25) 46(-5.5,-1.75) 47(-5.5,-2.25) 48(-5.5,-2.75)
  rect 0.36x0.8 smd: 49(-1.25,-2.65) 49(-1.25,2.65) 49(-0.75,-2.65) 49(-0.75,2.65) 49(-0.25,-2.65) 49(-0.25,2.65) 49(0.25,-2.65) 49(0.25,2.65) 49(0.75,-2.65) 49(0.75,2.65) 49(1.25,-2.65) 49(1.25,2.65)
  rect 7.3x7.3 smd: 49(0,0)
Top Layer:
  pour cut-out: -19.1,19.1 -14.45,19.1 -9.825,14.475 -5.25,9.83 -5.175,7.55 -4.95,7.25 -4.725,7.1 -4.475,7.05 4.475,7.05 4.7,7.1 4.875,7.2 4.95,7.25 4.975,7.275 5.075,7.4 5.175,7.6 5.2,7.75 5.2,9.55 5.225,9.7 5.25,9.8 5.3,9.9 5.375,10 5.425,10.075 5.475,10.125 5.575,10.225 14.45,19.1 19.1,19.1 19.1,14.45 10.05,5.4 9.975,5.35 9.9,5.3 9.85,5.275 9.65,5.2 7.775,5.2 7.55,5.15 7.425,5.1 7.375,5.075 7.225,4.925 7.175,4.85 7.125,4.775 7.1,4.725 7.075,4.65 7.05,4.55 7.05,-4.475 7.075,-4.625 7.1,-4.725 7.15,-4.825 7.2,-4.9 7.3,-5 7.425,-5.1 7.5,-5.125 7.6,-5.175 7.75,-5.2 9.5,-5.2 9.7,-5.225 9.775,-5.25 9.85,-5.275 9.95,-5.325 10.1,-5.45 19.1,-14.45 19.1,-19.1 14.45,-19.1 14.425,-19.075 5.425,-10.075 5.3,-9.9 5.25,-9.775 5.225,-9.7 5.2,-9.65 5.2,-7.7 5.175,-7.6 5.15,-7.55 5.125,-7.475 5.1,-7.425 5.05,-7.35 4.9,-7.2 4.8,-7.15 4.725,-7.1 4.65,-7.075 4.525,-7.05 -4.5,-7.05 -4.675,-7.1 -4.75,-7.125 -4.825,-7.15 -4.875,-7.2 -4.925,-7.225 -5.025,-7.325 -5.075,-7.4 -5.125,-7.475 -5.15,-7.55 -5.175,-7.625 -5.2,-7.725 -5.2,-9.525 -5.25,-9.8 -5.35,-10 -14.45,-19.1 -19.1,-19.1 -19.1,-14.45 -12.325,-7.675 -11.15,-6.5 -9.975,-5.35 -9.875,-5.275 -9.775,-5.25 -9.675,-5.2 -7.7,-5.2 -7.475,-5.125 -7.275,-4.975 -7.125,-4.75 -7.05,-4.475 -7.05,4.125 -7.075,4.6 -7.25,4.95 -7.6,5.175 -8.425,5.2 -9.5,5.2 -9.7,5.225 -9.875,5.275 -10.025,5.375 -11.9,7.25 -12.5,7.85 -15.8,11.15 -17.45,12.8 -19.1,14.45
Top Overlay:
  region: -5.5,-19.875 -4,-21.375 -7,-21.375
  lines w0.2: -19.05,-14.125 -19.05,14.2 ; -14.2,19.05 14.125,19.05 ; -14.125,-19.05 14.025,-19.05 ; 19.05,-14.025 19.05,14.125
Top Solder:
  region: -19.05,-19.05 -14.479,-19.05 -9.871,-14.443 -7.52,-12.08 -6.165,-10.736 -5.484,-10.056 -5.28,-9.8 -5.24,-9.55 -5.25,-9.3 -5.25,-7.8 -5.21,-7.49 -5.02,-7.24 -4.77,-7.04 -4.45,-7 4.45,-7 4.81,-7.05 5.05,-7.2 5.21,-7.48 5.25,-7.8 5.25,-9.49 5.3,-9.81 5.484,-10.056 14.479,-19.05 19.05,-19.05 19.05,-14.479 10.056,-5.484 9.8,-5.3 9.49,-5.25 7.8,-5.25 7.51,-5.19 7.26,-5.03 7.06,-4.77 7,-4.45 7,4.45 7.06,4.77 7.24,5.04 7.49,5.2 7.8,5.25 8.795,5.27 9.34,5.25 9.58,5.25 9.82,5.3 10.056,5.486 10.864,6.294 12.09,7.56 14.38,9.85 19.05,14.48 19.05,19.05 14.479,19.05 5.25,9.821 5.25,7.8 5.16,7.49 5.01,7.24 4.74,7.07 4.45,7 -4.45,7 -4.76,7.06 -5.04,7.23 -5.18,7.47 -5.25,7.8 -5.25,9.49 -5.32,9.81 -5.484,10.056 -14.479,19.05 -19.05,19.05 -19.05,14.479 -9.821,5.25 -7.8,5.25 -7.48,5.18 -7.22,4.99 -7.06,4.74 -7,4.45 -7,-4.45 -7.08,-4.78 -7.25,-5.04 -7.51,-5.18 -7.8,-5.25 -9.49,-5.25 -9.78,-5.3 -10.056,-5.484 -19.05,-14.479
  lines w0.1: -19.05,-19.05 -19.05,-14.479 -10.056,-5.484 cw(c-9.49,-6.05) -9.49,-5.25 -7.8,-5.25 ccw(c-7.8,-4.45) -7,-4.45 -7,4.45 ccw(c-7.8,4.45) -7.8,5.25 -9.49,5.25 cw(c-9.49,6.05) -10.056,5.484 -19.05,14.479 -19.05,19.05 -14.479,19.05 -5.484,10.056 cw(c-6.05,9.49) -5.25,9.49 -5.25,7.8 ccw(c-4.45,7.8) -4.45,7 4.45,7 ccw(c4.45,7.8) 5.25,7.8 5.25,9.49 cw(c6.05,9.49) 5.484,10.056 14.479,19.05 19.05,19.05 19.05,14.48 10.056,5.486 10.056,5.484 cw(c9.49,6.05) 9.49,5.25 7.8,5.25 ccw(c7.8,4.45) 7,4.45 7,-4.45 ccw(c7.8,-4.45) 7.8,-5.25 9.49,-5.25 cw(c9.49,-6.05) 10.056,-5.484 19.05,-14.479 19.05,-19.05 14.479,-19.05 5.484,-10.056 cw(c6.05,-9.49) 5.25,-9.49 5.25,-7.8 ccw(c4.45,-7.8) 4.45,-7 -4.45,-7 ccw(c-4.45,-7.8) -5.25,-7.8 -5.25,-9.49 cw(c-6.05,-9.49) -5.484,-10.056 -14.479,-19.05 -19.05,-19.05 ; -4,-4 4,-4 4,4 -4,4 -4,-4
M13_Assembly_Info:
  lines w0.1: -19.05,-19.05 -14.479,-19.05 -5.484,-10.056 ccw(c-6.05,-9.49) -5.25,-9.49 -5.25,-7.8 cw(c-4.45,-7.8) -4.45,-7 4.45,-7 cw(c4.45,-7.8) 5.25,-7.8 5.25,-9.49 ccw(c6.05,-9.49) 5.484,-10.056 14.479,-19.05 19.05,-19.05 19.05,-14.479 10.056,-5.484 ccw(c9.49,-6.05) 9.49,-5.25 7.8,-5.25 cw(c7.8,-4.45) 7,-4.45 7,4.45 cw(c7.8,4.45) 7.8,5.25 9.49,5.25 ccw(c9.49,6.05) 10.056,5.484 10.056,5.486 19.05,14.48 19.05,19.05 14.479,19.05 5.484,10.056 ccw(c6.05,9.49) 5.25,9.49 5.25,7.8 cw(c4.45,7.8) 4.45,7 -4.45,7 cw(c-4.45,7.8) -5.25,7.8 -5.25,9.49 ccw(c-6.05,9.49) -5.484,10.056 -14.479,19.05 -19.05,19.05 -19.05,14.479 -10.056,5.484 ccw(c-9.49,6.05) -9.49,5.25 -7.8,5.25 cw(c-7.8,4.45) -7,4.45 -7,-4.45 cw(c-7.8,-4.45) -7.8,-5.25 -9.49,-5.25 ccw(c-9.49,-6.05) -10.056,-5.484 -19.05,-14.479 -19.05,-19.05 ; -4,-4 -4,4 4,4 4,-4 -4,-4
M15_Country_Yard:
  lines w0.1: -0.5,0 0.5,0 ; 0,-0.5 0,0.5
